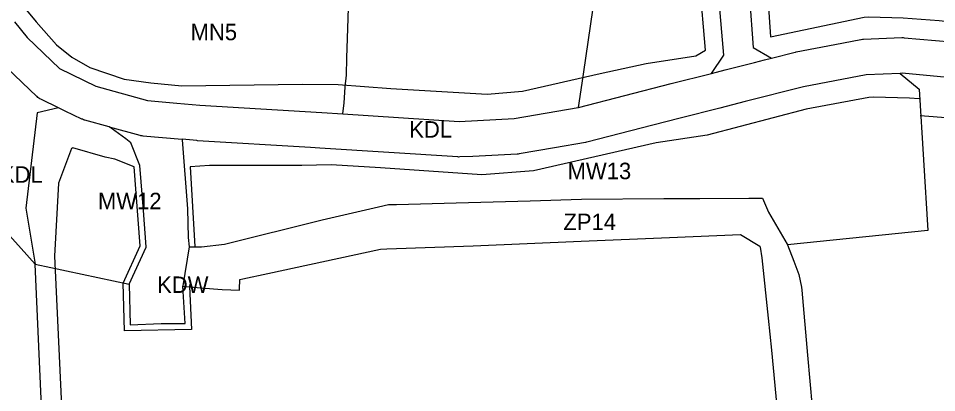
# Model space of a CAD drawing. Extents: x 7428080 to 7432143, y 5545880 to 5549217.
# Drawn here: x 7429340.3 to 7429649.7, y 5547932.8 to 5548058.7 of the extents above; entities that cross this region are included whole.
import ezdxf

# ---------------------------------------------------------------- set-up
doc = ezdxf.new("R2010")
doc.units = 0
for name, color, linetype in [('CZ_L_linie rozgraniczające tereny o różnym przeznaczeniu oraz różnych warunkach ich zabudowy i zagospodarowania', 7, 'Continuous'), ('CZ_L_maksymalne nieprzekraczalne linie zabudowy', 7, 'Continuous'), ('CZ_L_opisy_linie rozgraniczające tereny o różnym przeznaczeniu oraz różnych warunkach ich zabudowy i zagospodarowania', 7, 'Continuous')]:
    doc.layers.add(name, color=color, linetype=linetype)

msp = doc.modelspace()

# ---------------------------------------------------------------- linework, layer by layer
at = {"layer": 'CZ_L_linie rozgraniczające tereny o różnym przeznaczeniu oraz różnych warunkach ich zabudowy i zagospodarowania'}
for p, q in [((7429578.02, 5548046.38), (7429574.06, 5548092.42)), ((7429584.88, 5548089.06), (7429587.91, 5548048.88)), ((7429451.24, 5548052), (7429451.66, 5548065.75)), ((7429533.91, 5548062.3), (7429530.58, 5548039.93)), ((7429338.98, 5548057.54), (7429343.25, 5548052.27)), ((7429343.25, 5548052.27), (7429354.19, 5548041.8)), ((7429451.03, 5548045.49), (7429451.24, 5548052)), ((7429625.06, 5548051.71), (7429637.96, 5548052.24)), ((7429637.96, 5548052.24), (7429638.35, 5548052.24)), ((7429638.35, 5548052.24), (7429638.74, 5548052.22)), ((7429638.74, 5548052.22), (7429654.54, 5548050.78)), ((7429587.91, 5548048.88), (7429594.06, 5548045.36)), ((7429602.38, 5548047.46), (7429615.37, 5548049.93)), ((7429615.37, 5548049.93), (7429624.18, 5548051.61)), ((7429624.18, 5548051.61), (7429624.28, 5548051.63)), ((7429624.28, 5548051.63), (7429624.67, 5548051.69)), ((7429624.67, 5548051.69), (7429625.06, 5548051.71)), ((7429573.8, 5548040.21), (7429578.02, 5548046.38)), ((7429594.06, 5548045.36), (7429602.03, 5548047.38)), ((7429602.03, 5548047.38), (7429602.09, 5548047.4)), ((7429602.09, 5548047.4), (7429602.38, 5548047.46)), ((7429450.85, 5548039.57), (7429451.03, 5548045.49)), ((7429578.45, 5548041.39), (7429588.29, 5548043.89)), ((7429588.29, 5548043.89), (7429591.7, 5548044.76)), ((7429591.7, 5548044.76), (7429594.06, 5548045.36)), ((7429346.57, 5548032.47), (7429336.61, 5548042.02)), ((7429354.19, 5548041.8), (7429366.46, 5548035.87)), ((7429450.48, 5548035.64), (7429450.85, 5548039.57)), ((7429530.58, 5548039.93), (7429529.5, 5548032.48)), ((7429560.29, 5548036.78), (7429573.8, 5548040.21)), ((7429573.8, 5548040.21), (7429578.45, 5548041.39)), ((7429625.99, 5548039.74), (7429604.8, 5548035.71)), ((7429637.39, 5548040.2), (7429625.99, 5548039.74)), ((7429638.05, 5548040.23), (7429637.39, 5548040.2)), ((7429637.39, 5548040.2), (7429643.84, 5548034.85)), ((7429653.39, 5548038.84), (7429638.05, 5548040.23)), ((7429529.06, 5548028.73), (7429560.27, 5548036.78)), ((7429560.27, 5548036.78), (7429560.29, 5548036.78)), ((7429366.46, 5548035.87), (7429383.88, 5548031.12)), ((7429450.05, 5548030.17), (7429450.48, 5548035.64)), ((7429604.8, 5548035.71), (7429585.14, 5548030.71)), ((7429643.84, 5548034.85), (7429646.73, 5547987.36)), ((7429346.66, 5548032.39), (7429346.57, 5548032.47)), ((7429346.95, 5548032.14), (7429346.66, 5548032.39)), ((7429347.27, 5548031.9), (7429346.95, 5548032.14)), ((7429347.29, 5548031.88), (7429347.27, 5548031.9)), ((7429347.59, 5548031.69), (7429347.29, 5548031.88)), ((7429347.94, 5548031.49), (7429347.59, 5548031.69)), ((7429348.12, 5548031.4), (7429347.94, 5548031.49)), ((7429353.82, 5548028.65), (7429348.12, 5548031.4)), ((7429383.88, 5548031.12), (7429393.77, 5548030.23)), ((7429529.5, 5548032.48), (7429528.96, 5548028.71)), ((7429585.14, 5548030.71), (7429576.6, 5548028.54)), ((7429353.82, 5548028.65), (7429346.7, 5548026.92)), ((7429356.15, 5548027.53), (7429353.82, 5548028.65)), ((7429361.74, 5548024.83), (7429356.15, 5548027.53)), ((7429393.77, 5548030.23), (7429393.77, 5548030.23)), ((7429393.77, 5548030.23), (7429401.44, 5548029.54)), ((7429401.44, 5548029.54), (7429442.58, 5548027.06)), ((7429449.65, 5548026.74), (7429450.05, 5548030.17)), ((7429507.41, 5548024.97), (7429528.96, 5548028.71)), ((7429528.96, 5548028.71), (7429529.06, 5548028.73)), ((7429576.6, 5548028.54), (7429563.26, 5548025.16)), ((7429346.7, 5548026.92), (7429342.88, 5547994.84)), ((7429361.92, 5548024.75), (7429361.74, 5548024.83)), ((7429362.28, 5548024.6), (7429361.92, 5548024.75)), ((7429362.65, 5548024.48), (7429362.28, 5548024.6)), ((7429362.77, 5548024.44), (7429362.65, 5548024.48)), ((7429370.91, 5548022.22), (7429362.77, 5548024.44)), ((7429442.58, 5548027.06), (7429442.6, 5548027.06)), ((7429442.6, 5548027.06), (7429449.6, 5548026.6)), ((7429449.6, 5548026.6), (7429449.65, 5548026.74)), ((7429449.6, 5548026.6), (7429488.86, 5548024.07)), ((7429488.86, 5548024.07), (7429507.41, 5548024.97)), ((7429563.26, 5548025.16), (7429554.05, 5548022.78)), ((7429370.91, 5548022.22), (7429381.24, 5548019.4)), ((7429554.04, 5548022.78), (7429531.83, 5548017.05)), ((7429554.05, 5548022.78), (7429554.04, 5548022.78)), ((7429381.24, 5548019.4), (7429381.5, 5548019.34)), ((7429381.5, 5548019.34), (7429381.88, 5548019.26)), ((7429381.88, 5548019.26), (7429382.27, 5548019.22)), ((7429382.27, 5548019.22), (7429382.28, 5548019.22)), ((7429382.28, 5548019.22), (7429395.57, 5548018.02)), ((7429395.57, 5548018.02), (7429395.57, 5548017.83)), ((7429400.46, 5548017.58), (7429395.57, 5548018.02)), ((7429395.57, 5548017.83), (7429397.3, 5547994.66)), ((7429400.63, 5548017.56), (7429400.46, 5548017.58)), ((7429438.71, 5548015.27), (7429400.63, 5548017.56)), ((7429438.72, 5548015.27), (7429438.71, 5548015.27)), ((7429441.85, 5548015.08), (7429438.72, 5548015.27)), ((7429488.42, 5548012.07), (7429441.85, 5548015.08)), ((7429520.97, 5548015.14), (7429509.1, 5548013.08)), ((7429531.36, 5548016.95), (7429520.97, 5548015.14)), ((7429531.74, 5548017.03), (7429531.36, 5548016.95)), ((7429531.83, 5548017.05), (7429531.74, 5548017.03)), ((7429488.66, 5548012.06), (7429488.42, 5548012.07)), ((7429489.1, 5548012.07), (7429488.66, 5548012.06)), ((7429493.43, 5548012.28), (7429489.1, 5548012.07)), ((7429508.36, 5548013), (7429493.43, 5548012.28)), ((7429493.43, 5548012.28), (7429493.43, 5548012.28)), ((7429508.7, 5548013.02), (7429508.36, 5548013)), ((7429509.09, 5548013.08), (7429508.7, 5548013.02)), ((7429509.1, 5548013.08), (7429509.09, 5548013.08)), ((7429467.67, 5547996.1), (7429487.81, 5547996.62)), ((7429487.81, 5547996.62), (7429512.71, 5547997.32)), ((7429512.71, 5547997.32), (7429530.05, 5547997.85)), ((7429530.05, 5547997.85), (7429557.79, 5547998.07)), ((7429557.79, 5547998.07), (7429569.92, 5547998.14)), ((7429569.92, 5547998.14), (7429586.39, 5547998.22)), ((7429586.39, 5547998.22), (7429590.97, 5547998.21)), ((7429590.97, 5547998.21), (7429593.07, 5547993.54)), ((7429342.88, 5547994.84), (7429345.98, 5547976.01)), ((7429397.3, 5547994.66), (7429397.5, 5547984.96)), ((7429442.68, 5547990.93), (7429461.7, 5547995.28)), ((7429461.7, 5547995.28), (7429464.97, 5547996.03)), ((7429464.97, 5547996.03), (7429467.67, 5547996.1)), ((7429593.07, 5547993.54), (7429594.65, 5547990.8)), ((7429409.76, 5547982.75), (7429442.68, 5547990.93)), ((7429594.65, 5547990.8), (7429599.31, 5547982.72)), ((7429646.73, 5547987.36), (7429599.4, 5547982.5)), ((7429337.38, 5547985.6), (7429341.26, 5547981.26)), ((7429397.5, 5547984.96), (7429397.82, 5547981.78)), ((7429529.88, 5547983.73), (7429559.65, 5547985.02)), ((7429559.65, 5547985.02), (7429583.58, 5547985.93)), ((7429583.58, 5547985.93), (7429590.15, 5547982.05)), ((7429341.26, 5547981.26), (7429345.98, 5547976.01)), ((7429397.82, 5547981.78), (7429395.75, 5547968.65)), ((7429397.82, 5547981.78), (7429402.01, 5547981.87)), ((7429402.01, 5547981.87), (7429409.76, 5547982.75)), ((7429424.37, 5547972.83), (7429462.31, 5547981.03)), ((7429462.31, 5547981.03), (7429464.52, 5547981.17)), ((7429464.52, 5547981.17), (7429493.52, 5547982.19)), ((7429493.52, 5547982.19), (7429529.88, 5547983.73)), ((7429590.15, 5547982.05), (7429590.19, 5547981.76)), ((7429590.19, 5547981.76), (7429590.75, 5547978.1)), ((7429599.31, 5547982.72), (7429599.4, 5547982.5)), ((7429599.4, 5547982.5), (7429601.59, 5547977.01)), ((7429590.75, 5547978.1), (7429592.98, 5547957.86)), ((7429350.22, 5547883.45), (7429345.98, 5547976.01)), ((7429345.98, 5547976.01), (7429377.7, 5547969.21)), ((7429601.59, 5547977.01), (7429603.24, 5547972.5)), ((7429415.96, 5547971.02), (7429424.37, 5547972.83)), ((7429603.24, 5547972.5), (7429604.21, 5547968.25)), ((7429377.7, 5547969.21), (7429378.03, 5547955.59)), ((7429395.75, 5547968.65), (7429395.76, 5547968.62)), ((7429395.76, 5547968.62), (7429401.75, 5547968.05)), ((7429396.57, 5547955.99), (7429395.76, 5547968.62)), ((7429414.81, 5547967.61), (7429414.89, 5547970.79)), ((7429414.89, 5547970.79), (7429415.96, 5547971.02)), ((7429401.75, 5547968.05), (7429409.04, 5547967.47)), ((7429409.04, 5547967.47), (7429414.8, 5547967.25)), ((7429414.8, 5547967.25), (7429414.81, 5547967.61)), ((7429604.21, 5547968.25), (7429604.28, 5547967.25)), ((7429604.28, 5547967.25), (7429606.13, 5547945.39)), ((7429592.98, 5547957.86), (7429594.05, 5547947.07)), ((7429378.03, 5547955.59), (7429388.43, 5547955.98)), ((7429388.43, 5547955.98), (7429396.57, 5547955.99)), ((7429594.05, 5547947.07), (7429596.27, 5547923.71)), ((7429606.13, 5547945.39), (7429607.73, 5547927.86))]:
    msp.add_line(p, q, dxfattribs=at)
for points in [[(7429377.7, 5547969.21), (7429383.38, 5547981.73), (7429383.39, 5547981.82), (7429383.4, 5547981.88), (7429382.46, 5547994.11), (7429381.3, 5548009.24), (7429378.2, 5548016.8), (7429376.59, 5548018.18), (7429371.59, 5548021.73), (7429370.91, 5548022.22)], [(7429377.7, 5547969.21), (7429377.7, 5547969.21)]]:
    msp.add_lwpolyline(points, dxfattribs=at)
at = {"layer": 'CZ_L_maksymalne nieprzekraczalne linie zabudowy'}
for points in [[(7429737.56, 5548266.68), (7429712.6, 5548265.77), (7429657.63, 5548261.19), (7429626.79, 5548257.94), (7429606.97, 5548255.66), (7429606.31, 5548255.44), (7429604.61, 5548253.44), (7429611.04, 5548115.65), (7429608.73, 5548101.41), (7429605.47, 5548096.04), (7429602.01, 5548092.86), (7429597.64, 5548091.02), (7429592.48, 5548090.26), (7429591.2, 5548089.04), (7429593.66, 5548052.51), (7429625.28, 5548059.08), (7429626.81, 5548059.19), (7429638.42, 5548058.91), (7429650.51, 5548058.04), (7429686.57, 5548053.92), (7429706.66, 5548051.95), (7429717.21, 5548051.09), (7429737.76, 5548049.93)], [(7429340.85, 5548064.2), (7429346.35, 5548057.51), (7429353.23, 5548049.82), (7429358.36, 5548045.7), (7429364.4, 5548042.17), (7429375.97, 5548038.21), (7429385.01, 5548037.04), (7429395.45, 5548036.04), (7429435.96, 5548036.53), (7429448.02, 5548036.49), (7429465.85, 5548035.1), (7429498.32, 5548033.26), (7429510.21, 5548034.23), (7429536.34, 5548040.2), (7429551.86, 5548043.57), (7429568.56, 5548046.08), (7429571.86, 5548048), (7429568.03, 5548092.53)], [(7429643.75, 5548031.59), (7429640.58, 5548031.85), (7429628.44, 5548032.16), (7429626.82, 5548032.05), (7429605.74, 5548028.13), (7429572.41, 5548019.42), (7429555.2, 5548016.89), (7429513.82, 5548007.36), (7429496.48, 5548006.06), (7429462.35, 5548008.44), (7429445.74, 5548009.4), (7429435.79, 5548009.25), (7429404.67, 5548009.24), (7429398.24, 5548008.81), (7429399.82, 5547981.97)], [(7429807.79, 5548025.22), (7429785.86, 5548020.87), (7429764.76, 5548017.83), (7429756.34, 5548017.17), (7429740.83, 5548016.75), (7429725.46, 5548016.89), (7429688.59, 5548020.99), (7429654.28, 5548025.17), (7429644.09, 5548025.88)], [(7429398.06, 5547969.24), (7429397.95, 5547968.51), (7429398.7, 5547953.99), (7429376.08, 5547953.52), (7429375.68, 5547969.6), (7429381.37, 5547982.15), (7429379.33, 5548008.77), (7429372.88, 5548011.31), (7429369.61, 5548012.02), (7429358.71, 5548015.17), (7429358.22, 5548014.9), (7429353.84, 5548003.28), (7429352.52, 5547978.68), (7429357.02, 5547882.63), (7429420.25, 5547781.76)]]:
    msp.add_lwpolyline(points, dxfattribs=at)

# ---------------------------------------------------------------- texts
at = {"layer": 'CZ_L_opisy_linie rozgraniczające tereny o różnym przeznaczeniu oraz różnych warunkach ich zabudowy i zagospodarowania'}
for s, p in [('MN5', (7429398.35, 5548051.37)), ('KDL', (7429472.02, 5548018.58)), ('KDL', (7429334.12, 5548003.4)), ('MW13', (7429525.35, 5548004.6)), ('MW12', (7429367.14, 5547994.48)), ('ZP14', (7429523.94, 5547987.46)), ('KDW', (7429387.06, 5547966.31))]:
    msp.add_text(s, height=5.549, dxfattribs=at).set_placement(p)

doc.saveas('drawing.dxf')
